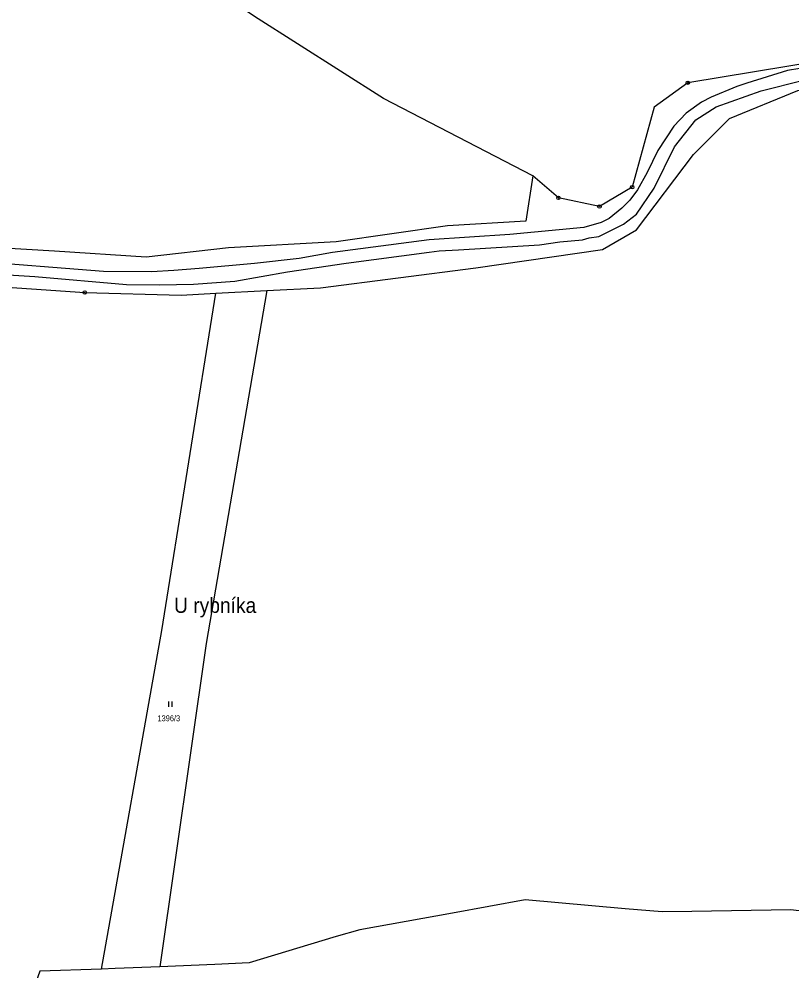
# Model space of a CAD drawing. Extents: x -872229 to -869198, y -1075981 to -1074329.
# Drawn here: x -870264.8 to -870040, y -1075213.2 to -1074936.4 of the extents above; entities that cross this region are included whole.
import ezdxf

# ---------------------------------------------------------------- set-up
doc = ezdxf.new("R2010")
doc.units = 0
doc.header["$LTSCALE"] = 0.68
for name, color, linetype, lineweight in [('1', 7, 'Continuous', 25), ('3', 7, 'Continuous', 25), ('7', 7, 'Continuous', 13), ('8', 7, 'Continuous', 25)]:
    doc.layers.add(name, color=color, linetype=linetype, lineweight=lineweight)
doc.layers.add('2', color=7, linetype='Continuous')

msp = doc.modelspace()

# ---------------------------------------------------------------- linework, layer by layer
at = {"layer": '1'}
msp.add_line((-870207.57, -1075016.13), (-870192.71, -1075015.36), dxfattribs=at)
for points in [[(-870115.36, -1074981.96), (-870158.79, -1074959.47), (-870196.33, -1074935.63), (-870230.5, -1074912.24), (-870256.59, -1074884.78)], [(-869972.29, -1074950.57), (-870021.54, -1074946.89), (-870070.32, -1074954.92), (-870080.13, -1074961.97), (-870086.48, -1074985.27), (-870095.97, -1074990.9), (-870107.93, -1074988.38), (-870115.36, -1074981.96)], [(-870030.59, -1074949.58), (-870041.3, -1074951.38), (-870053.18, -1074955.05), (-870056.07, -1074956.04), (-870063.55, -1074959.11), (-870066.35, -1074960.52), (-870070.78, -1074963.79), (-870074.34, -1074967.55), (-870078.98, -1074974.57), (-870082.13, -1074981.03), (-870084.98, -1074986.04), (-870087.13, -1074989.06), (-870089.45, -1074991.41), (-870093.2, -1074994.42), (-870095.52, -1074995.57), (-870100.55, -1074997.01), (-870122.06, -1074999.05), (-870145.48, -1075000.6), (-870173.64, -1075004.3), (-870183.32, -1075006.02), (-870196.34, -1075007.51), (-870212.39, -1075008.9), (-870219.73, -1075009.49), (-870226.27, -1075009.94), (-870240.2, -1075009.79), (-870279.52, -1075006.66)], [(-870427.04, -1075000.9), (-870260.16, -1075011.3), (-870233.53, -1075013.54), (-870223.87, -1075013.7), (-870214.03, -1075013.5), (-870201.98, -1075012.58), (-870186.67, -1075009.93), (-870169.68, -1075007.4), (-870145.53, -1075004.18), (-870142.58, -1075003.79), (-870136.98, -1075003.46), (-870113.41, -1075002.07), (-870107.51, -1075001.22), (-870100.88, -1075000.55), (-870098.94, -1074999.98), (-870096.16, -1074999.58), (-870088.97, -1074996.08), (-870085.25, -1074993.1), (-870080.09, -1074985.61), (-870074.16, -1074973.56), (-870067.97, -1074965.73), (-870062.07, -1074961.95), (-870048.94, -1074957.25), (-870036.64, -1074954.16)], [(-870192.71, -1075015.36), (-870177.13, -1075014.56), (-870131.91, -1075008.73), (-870095.14, -1075003.44), (-870085.27, -1074997.72), (-870068.68, -1074975.81), (-870058.23, -1074965.32), (-870038.32, -1074957.19), (-870023.13, -1074956.23), (-870015.04, -1074962.59), (-870008.3, -1074975.45), (-870007.09, -1074982.34), (-870000.81, -1074953.44)], [(-870115.36, -1074981.96), (-870117.37, -1074995.15), (-870140.21, -1074996.52), (-870172.56, -1075001.14), (-870203.84, -1075002.96), (-870227.79, -1075005.61), (-870254.49, -1075003.89), (-870314.81, -1075000.31), (-870361.75, -1074998.26), (-870391.78, -1074996.03), (-870411.2, -1074993.72), (-870422.25, -1074993.21), (-870453.27, -1074990.57), (-870470.34, -1074988.35), (-870494.98, -1074984.19), (-870516.43, -1074977.89), (-870524.35, -1074974.36)], [(-870610.36, -1075011.6), (-870588.87, -1075001.44), (-870569.21, -1074993.58), (-870546.64, -1074988.8), (-870536.79, -1074988.15), (-870527.6, -1074989.88), (-870515.91, -1074994.03), (-870492.69, -1074997.19), (-870452.83, -1075001.97), (-870413.18, -1075005.54), (-870363.54, -1075007.87), (-870304.97, -1075011.83), (-870245.64, -1075015.91), (-870217.62, -1075016.65), (-870207.57, -1075016.13)], [(-870240.81, -1075212.65), (-870223.28, -1075114.2), (-870207.57, -1075016.13)], [(-870192.71, -1075015.36), (-870210.36, -1075117.93), (-870223.81, -1075211.98)], [(-870032.43, -1075196.35), (-870040.36, -1075195.42), (-870069.16, -1075195.89), (-870077.74, -1075196.02), (-870088.54, -1075195.1), (-870117.61, -1075192.53), (-870138.77, -1075196.42), (-870165.66, -1075201.23), (-870172.52, -1075203.21), (-870197.84, -1075210.79), (-870207.87, -1075211.32), (-870223.81, -1075211.98)], [(-870240.81, -1075212.65), (-870258.69, -1075213.29), (-870266.01, -1075233.81), (-870266.41, -1075236.59), (-870273.27, -1075250.11), (-870290.79, -1075252.03), (-870312.54, -1075249.92), (-870321.52, -1075248.92), (-870324.09, -1075248.79), (-870341.63, -1075252.94), (-870351.93, -1075255.06), (-870365.6, -1075255.58)], [(-870223.81, -1075211.98), (-870236.81, -1075212.51), (-870240.81, -1075212.65)]]:
    msp.add_lwpolyline(points, dxfattribs=at)
at = {"layer": '3'}
for p, q in [((-870221.241, -1075136.36), (-870221.241, -1075134.86)), ((-870220.24, -1075136.36), (-870220.24, -1075134.86))]:
    msp.add_line(p, q, dxfattribs=at)
at = {"layer": '8'}
for centre, radius in [((-870070.32, -1074954.9199), 0.5), ((-870070.32, -1074954.9199), 0.0303), ((-870086.48, -1074985.2699), 0.5), ((-870086.48, -1074985.2699), 0.0303), ((-870107.93, -1074988.3799), 0.5), ((-870107.93, -1074988.3799), 0.0303), ((-870095.97, -1074990.8999), 0.5), ((-870095.97, -1074990.8999), 0.0303), ((-870245.64, -1075015.9099), 0.5), ((-870245.64, -1075015.9099), 0.0303)]:
    msp.add_circle(centre, radius, dxfattribs=at)

# ---------------------------------------------------------------- texts
at = {"layer": '2', "width": 0.95}
msp.add_text('1396/3', height=1.7, dxfattribs=at).set_placement((-870224.51, -1075140.58))
at = {"layer": '7', "width": 0.95}
msp.add_text('U rybníka', height=4.4, dxfattribs=at).set_placement((-870219.69, -1075109.08))

doc.saveas('drawing.dxf')
